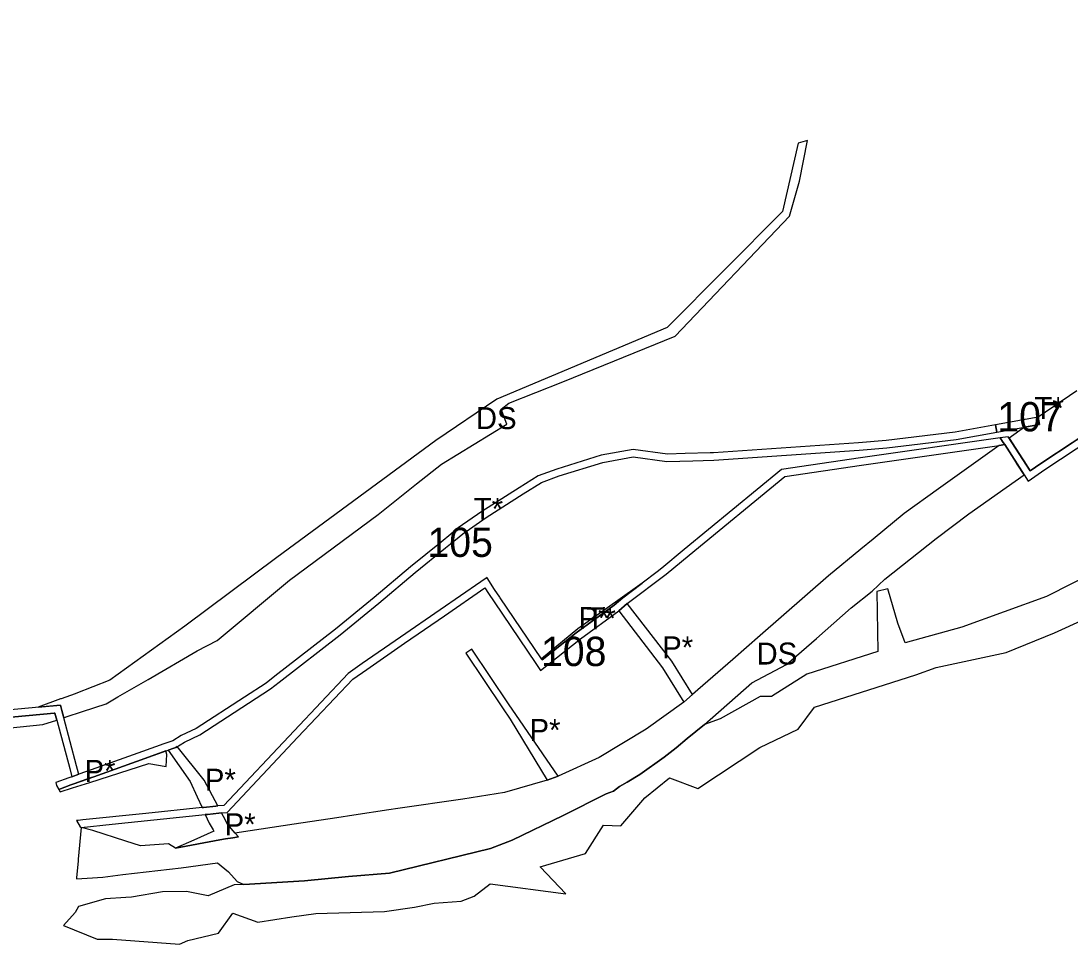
# Model space of a CAD drawing. Extents: x -477304 to -465641, y -1159113 to -1149285.
# Drawn here: x -476117.4 to -475687.9, y -1154887 to -1154509.2 of the extents above; entities that cross this region are included whole.
import ezdxf

# ---------------------------------------------------------------- set-up
doc = ezdxf.new("R2010")
doc.units = 0
for name, color, linetype in [('22', 7, 'Continuous'), ('34', 7, 'Continuous'), ('35', 7, 'Continuous'), ('4', 7, 'Continuous'), ('60', 7, 'Continuous')]:
    doc.layers.add(name, color=color, linetype=linetype)

msp = doc.modelspace()

# ---------------------------------------------------------------- linework, layer by layer
at = {"layer": '22'}
for p, q in [((-475758.44, -1154755.69), (-475762.53, -1154741.69)), ((-475697.53, -1154744.77), (-475732.26, -1154757.29)), ((-475714.08, -1154767.75), (-475694.3, -1154759.7)), ((-475792.53, -1154790), (-475751.05, -1154776.76)), ((-475799.22, -1154799.01), (-475792.53, -1154790)), ((-475849.2, -1154806.7), (-475854.13, -1154810.46)), ((-475844.63, -1154802.88), (-475849.2, -1154806.7)), ((-475854.13, -1154810.46), (-475864.07, -1154817.55)), ((-475861.99, -1154827.13), (-475851.92, -1154818.99)), ((-475851.92, -1154818.99), (-475840.29, -1154823.32)), ((-475874.75, -1154824.37), (-475877.78, -1154825.48)), ((-475916.35, -1154844.45), (-475925.17, -1154847.88)), ((-475925.17, -1154847.88), (-475966.49, -1154857.95)), ((-475894.38, -1154866.48), (-475904.83, -1154855.44)), ((-476030.13, -1154862.72), (-476040.75, -1154867.29)), ((-475931.84, -1154867.36), (-475925.32, -1154862.34)), ((-475925.32, -1154862.34), (-475894.38, -1154866.48)), ((-476040.75, -1154867.29), (-476049.61, -1154865.49)), ((-476095.23, -1154874.14), (-476099.93, -1154879.38)), ((-476099.93, -1154879.38), (-476086.18, -1154884.99)), ((-476049.12, -1154885.62), (-476036.49, -1154882.49)), ((-476086.18, -1154884.99), (-476079.85, -1154885.05))]:
    msp.add_line(p, q, dxfattribs=at)
for points in [[(-475641.33, -1154712.54), (-475655.75, -1154723.67), (-475697.53, -1154744.77)], [(-475694.3, -1154759.7), (-475671.25, -1154749.19), (-475628.72, -1154721.46), (-475627.32, -1154720.53)], [(-475762.53, -1154741.69), (-475767.02, -1154742.69), (-475766.62, -1154767.26), (-475795.73, -1154776.52), (-475810.07, -1154785.67), (-475814.8, -1154785.73), (-475831.1, -1154794.9), (-475837.59, -1154797.1), (-475844.63, -1154802.88)], [(-475732.26, -1154757.29), (-475755.4, -1154763.75), (-475758.44, -1154755.69)], [(-475751.05, -1154776.76), (-475742.66, -1154773.84), (-475714.08, -1154767.75)], [(-475840.29, -1154823.32), (-475814.86, -1154806.55), (-475799.22, -1154799.01)], [(-475864.07, -1154817.55), (-475869.24, -1154820.78), (-475872.38, -1154822.57), (-475874.75, -1154824.37)], [(-475877.78, -1154825.48), (-475895.41, -1154834.42), (-475916.35, -1154844.45)], [(-475878.85, -1154838.35), (-475871.78, -1154838.63), (-475861.99, -1154827.13)], [(-475904.83, -1154855.44), (-475886.23, -1154849.97), (-475878.85, -1154838.35)], [(-475966.49, -1154857.95), (-475983.34, -1154859.42), (-476001.3, -1154861.14)], [(-476001.3, -1154861.14), (-476026.13, -1154862.63), (-476030.13, -1154862.72)], [(-476049.61, -1154865.49), (-476059.4, -1154865.62), (-476072.2, -1154867.83), (-476074.44, -1154868), (-476082.72, -1154868.56), (-476093.86, -1154871.59), (-476095.23, -1154874.14)], [(-475968.58, -1154873.72), (-475956.34, -1154871.9), (-475948.19, -1154870.34), (-475937.16, -1154869.49), (-475931.84, -1154867.36)], [(-476036.49, -1154882.49), (-476030.59, -1154874.38), (-476020.4, -1154878.03), (-476006.43, -1154875.93)], [(-476006.43, -1154875.93), (-475996.67, -1154874.47), (-475968.58, -1154873.72)], [(-476079.85, -1154885.05), (-476052.52, -1154886.99), (-476049.12, -1154885.62)]]:
    msp.add_lwpolyline(points, dxfattribs=at)
at = {"layer": '34'}
for p, q in [((-475863.11, -1154739.28), (-475873.1, -1154746.39)), ((-475871.05, -1154745.28), (-475863.11, -1154739.28)), ((-475873.1, -1154746.39), (-475889.39, -1154757.98)), ((-475869.17, -1154747.62), (-475872.68, -1154750.6)), ((-475872.68, -1154750.6), (-475854.76, -1154773.95)), ((-475850.93, -1154771.26), (-475869.17, -1154747.62)), ((-475889.39, -1154757.98), (-475904.3, -1154770.25)), ((-475842.46, -1154784.88), (-475850.93, -1154771.26)), ((-475854.76, -1154773.95), (-475846.08, -1154788.04)), ((-475846.08, -1154788.04), (-475842.46, -1154784.88)), ((-475920.24, -1154790.36), (-475917.13, -1154794.99)), ((-475917.13, -1154794.99), (-475901.97, -1154819.95)), ((-476054.43, -1154806.66), (-476057.17, -1154807.64)), ((-476042.39, -1154819.88), (-476053.38, -1154806.14)), ((-476057.66, -1154809.45), (-476058.1, -1154807.98)), ((-476057.88, -1154814.34), (-476057.66, -1154809.45)), ((-476057.17, -1154807.64), (-476048.12, -1154820.49)), ((-476088.97, -1154819.02), (-476095.75, -1154821.47)), ((-476087.62, -1154818.53), (-476088.97, -1154819.02)), ((-476036.75, -1154830.49), (-476042.39, -1154819.88)), ((-475901.97, -1154819.95), (-475897.47, -1154818.33)), ((-476101.91, -1154823.69), (-476101.3, -1154824.75)), ((-476048.12, -1154820.49), (-476045.25, -1154826.76)), ((-476045.25, -1154826.76), (-476043.25, -1154831.16)), ((-476043.25, -1154831.16), (-476042.67, -1154831.1)), ((-476042.67, -1154831.1), (-476037.62, -1154830.58)), ((-476037.62, -1154830.58), (-476036.75, -1154830.49)), ((-476040.98, -1154833.94), (-476041.95, -1154834.04)), ((-476041.95, -1154834.04), (-476040.36, -1154837.54)), ((-476036.33, -1154833.46), (-476040.98, -1154833.94)), ((-476035.24, -1154833.35), (-476036.33, -1154833.46)), ((-476034.43, -1154834.87), (-476035.24, -1154833.35)), ((-476032.81, -1154837.91), (-476034.43, -1154834.87)), ((-476038.46, -1154840.8), (-476046.61, -1154844.46)), ((-476040.36, -1154837.54), (-476038.76, -1154840.3)), ((-476038.76, -1154840.3), (-476038.46, -1154840.8)), ((-476029.68, -1154841.62), (-476032.81, -1154837.91)), ((-476054.11, -1154847.83), (-476035.96, -1154844.3)), ((-476046.61, -1154844.46), (-476054.11, -1154847.83)), ((-476035.96, -1154844.3), (-476033.65, -1154843.9)), ((-476033.65, -1154843.9), (-476030.7, -1154843.48)), ((-476030.7, -1154843.48), (-476028.39, -1154843.15)), ((-476028.39, -1154843.15), (-476029.68, -1154841.62))]:
    msp.add_line(p, q, dxfattribs=at)
for points in [[(-475904.3, -1154770.25), (-475904.15, -1154770.49), (-475904, -1154770.7), (-475890.09, -1154759.68), (-475874.54, -1154748.25), (-475871.05, -1154745.28)], [(-475934, -1154767.16), (-475935.24, -1154767.99), (-475920.24, -1154790.36)], [(-475897.47, -1154818.33), (-475917.76, -1154788.68), (-475932.75, -1154766.33), (-475934, -1154767.16)], [(-476053.38, -1154806.14), (-476053.98, -1154806.5), (-476054.43, -1154806.66)], [(-476058.1, -1154807.98), (-476066.67, -1154811.07), (-476087.62, -1154818.53)], [(-476089.16, -1154820.83), (-476065.05, -1154813.06), (-476057.88, -1154814.34)], [(-476095.75, -1154821.47), (-476096.97, -1154821.91), (-476101.91, -1154823.69)], [(-476101.3, -1154824.75), (-476096.32, -1154823.14), (-476089.16, -1154820.83)]]:
    msp.add_lwpolyline(points, dxfattribs=at)
at = {"layer": '35'}
for p, q in [((-475685.2, -1154660.63), (-475700.93, -1154671.42)), ((-475922.61, -1154664.03), (-475947.5, -1154680.92)), ((-475918.51, -1154674.28), (-475920.8, -1154668.13)), ((-475699.88, -1154690.36), (-475667.77, -1154669.13)), ((-475700.93, -1154671.42), (-475700.4, -1154674.37)), ((-475945.25, -1154690.59), (-475918.51, -1154674.28)), ((-475706.58, -1154675.47), (-475712.81, -1154679.95)), ((-475700.4, -1154674.37), (-475706.58, -1154675.47)), ((-475947.5, -1154680.92), (-476012.67, -1154728.85)), ((-475712.81, -1154679.95), (-475707.37, -1154688.4)), ((-475716.95, -1154682.93), (-475741.77, -1154700.75)), ((-475714.68, -1154682.6), (-475716.95, -1154682.93)), ((-475709.85, -1154690.08), (-475714.68, -1154682.6)), ((-475955.49, -1154698.67), (-475945.25, -1154690.59)), ((-475709.83, -1154690.12), (-475709.85, -1154690.08)), ((-475709.81, -1154690.15), (-475709.83, -1154690.12)), ((-475709.26, -1154690.99), (-475709.81, -1154690.15)), ((-475706.66, -1154695.02), (-475709.26, -1154690.99)), ((-475707.37, -1154688.4), (-475707.35, -1154688.42)), ((-475707.35, -1154688.42), (-475706.8, -1154689.27)), ((-475706.8, -1154689.27), (-475704.19, -1154693.32)), ((-475704.19, -1154693.32), (-475699.88, -1154690.36)), ((-475714.09, -1154700.11), (-475706.66, -1154695.02)), ((-475971.18, -1154711.25), (-475955.49, -1154698.67)), ((-475741.77, -1154700.75), (-475755.82, -1154710.84)), ((-476007.43, -1154738.07), (-475971.18, -1154711.25)), ((-475755.82, -1154710.84), (-475768.54, -1154721.28)), ((-475773.59, -1154725.43), (-475786.81, -1154736.27)), ((-475768.54, -1154721.28), (-475773.59, -1154725.43)), ((-476012.67, -1154728.85), (-476050.28, -1154756.97)), ((-476037, -1154762.78), (-476007.43, -1154738.07)), ((-475786.81, -1154736.27), (-475814.84, -1154760.76)), ((-475768.86, -1154742.57), (-475763.79, -1154737.64)), ((-476050.28, -1154756.97), (-476081.05, -1154779.07)), ((-476045.28, -1154767.03), (-476037, -1154762.78)), ((-475814.84, -1154760.76), (-475825.98, -1154770.49)), ((-475804.04, -1154772.54), (-475791.68, -1154761.94)), ((-475825.98, -1154770.49), (-475840.27, -1154782.97)), ((-476095.21, -1154784.55), (-476100.9, -1154786.6)), ((-475842.46, -1154784.88), (-475846.08, -1154788.04)), ((-475840.27, -1154782.97), (-475842.46, -1154784.88)), ((-476101.2, -1154786.71), (-476110.36, -1154790.12)), ((-476100.9, -1154786.6), (-476101.2, -1154786.71)), ((-475846.08, -1154788.04), (-475861.5, -1154799)), ((-476100.64, -1154791.48), (-476099.87, -1154794.38)), ((-476099.87, -1154794.38), (-476098.93, -1154794.07)), ((-476098.93, -1154794.07), (-476092.16, -1154791.84)), ((-476133.97, -1154799.67), (-476108.48, -1154797.21)), ((-476108.48, -1154797.21), (-476102.72, -1154795.32)), ((-475861.5, -1154799), (-475880.64, -1154810.64)), ((-475880.64, -1154810.64), (-475897.47, -1154818.33)), ((-475897.47, -1154818.33), (-475901.97, -1154819.95)), ((-475869.24, -1154820.78), (-475864.07, -1154817.55)), ((-475901.97, -1154819.95), (-475919.37, -1154824.97)), ((-475872.38, -1154822.57), (-475869.24, -1154820.78)), ((-475936.55, -1154827.75), (-475963.04, -1154831.53)), ((-475919.37, -1154824.97), (-475936.55, -1154827.75)), ((-475963.04, -1154831.53), (-475966.77, -1154832.06)), ((-475988.12, -1154835.3), (-476005.51, -1154837.95)), ((-476074.46, -1154844.88), (-476087.95, -1154840.53)), ((-476068.39, -1154846.84), (-476074.46, -1154844.88)), ((-476035.96, -1154844.3), (-476054.11, -1154847.83)), ((-476033.65, -1154843.9), (-476035.96, -1154844.3)), ((-476030.7, -1154843.48), (-476033.65, -1154843.9)), ((-476028.39, -1154843.15), (-476030.7, -1154843.48)), ((-476029.68, -1154841.62), (-476028.39, -1154843.15)), ((-475925.17, -1154847.88), (-475916.35, -1154844.45)), ((-476057.03, -1154845.94), (-476068.39, -1154846.84)), ((-476054.11, -1154847.83), (-476057.03, -1154845.94)), ((-475966.49, -1154857.95), (-475925.17, -1154847.88)), ((-476051.82, -1154855.83), (-476036.88, -1154853.74)), ((-476036.88, -1154853.74), (-476032.42, -1154857.45)), ((-476083.9, -1154859.63), (-476075.68, -1154858.55)), ((-476075.68, -1154858.55), (-476051.82, -1154855.83)), ((-476032.42, -1154857.45), (-476028.91, -1154861.43)), ((-475983.34, -1154859.42), (-475966.49, -1154857.95)), ((-476094.7, -1154860.3), (-476090.22, -1154860.02)), ((-476090.22, -1154860.02), (-476083.9, -1154859.63)), ((-476028.91, -1154861.43), (-476026.13, -1154862.63))]:
    msp.add_line(p, q, dxfattribs=at)
for points in [[(-475799.19, -1154559.23), (-475805.67, -1154587.21), (-475852.85, -1154634.72), (-475922.61, -1154664.03)], [(-475798.7, -1154574.83), (-475795.44, -1154558.14), (-475799.19, -1154559.23)], [(-475920.8, -1154668.13), (-475917.69, -1154665.67), (-475895.52, -1154656.98), (-475849.57, -1154638.2), (-475802.7, -1154589.18), (-475798.7, -1154574.83)], [(-475763.79, -1154737.64), (-475742.69, -1154721.08), (-475729.35, -1154710.9), (-475714.09, -1154700.11)], [(-475791.68, -1154761.94), (-475777.51, -1154749.36), (-475768.86, -1154742.57)], [(-476077.71, -1154785.89), (-476065.3, -1154778.67), (-476045.28, -1154767.03)], [(-475837.59, -1154797.1), (-475818.14, -1154780.14), (-475804.04, -1154772.54)], [(-476081.05, -1154779.07), (-476094.92, -1154784.44), (-476095.21, -1154784.55)], [(-476110.36, -1154790.12), (-476101.23, -1154789.27), (-476101.1, -1154789.74), (-476100.64, -1154791.48)], [(-476092.16, -1154791.84), (-476082.55, -1154788.68), (-476077.71, -1154785.89)], [(-476103.83, -1154792.52), (-476103.86, -1154792.53), (-476131.8, -1154795.14), (-476148.76, -1154794.9)], [(-476102.72, -1154795.32), (-476103.48, -1154792.49), (-476103.83, -1154792.52)], [(-475864.07, -1154817.55), (-475854.13, -1154810.46), (-475849.2, -1154806.7), (-475844.63, -1154802.88), (-475837.59, -1154797.1)], [(-475877.78, -1154825.48), (-475874.75, -1154824.37), (-475872.38, -1154822.57)], [(-475916.35, -1154844.45), (-475895.41, -1154834.42), (-475877.78, -1154825.48)], [(-475966.77, -1154832.06), (-475981.14, -1154834.24), (-475988.12, -1154835.3)], [(-476087.95, -1154840.53), (-476092.69, -1154839.28), (-476093.92, -1154852.23), (-476094, -1154853.04), (-476094.65, -1154859.83), (-476094.7, -1154860.3)], [(-476005.51, -1154837.95), (-476028.03, -1154841.35), (-476029.68, -1154841.62)], [(-476026.13, -1154862.63), (-476001.3, -1154861.14), (-475983.34, -1154859.42)]]:
    msp.add_lwpolyline(points, dxfattribs=at)
at = {"layer": '4'}
for p, q in [((-475700.93, -1154671.42), (-475718.46, -1154674.55)), ((-475700.4, -1154674.37), (-475700.93, -1154671.42)), ((-475718.46, -1154674.55), (-475735.01, -1154677.5)), ((-475718.46, -1154674.55), (-475717.93, -1154677.5)), ((-475717.93, -1154677.5), (-475718.46, -1154674.55)), ((-475717.93, -1154677.5), (-475700.4, -1154674.37)), ((-475716.47, -1154679.83), (-475773.69, -1154688.08)), ((-475713.2, -1154679.36), (-475716.47, -1154679.83)), ((-475715.25, -1154681.71), (-475716.47, -1154679.83)), ((-475716.47, -1154679.83), (-475715.25, -1154681.71)), ((-475714.68, -1154682.6), (-475715.25, -1154681.71)), ((-475715.25, -1154681.71), (-475714.68, -1154682.6)), ((-475704.19, -1154693.32), (-475713.2, -1154679.36)), ((-475866.8, -1154684.59), (-475879.92, -1154686.96)), ((-475835.29, -1154686.01), (-475845.49, -1154686.3)), ((-475773.32, -1154691.06), (-475716.95, -1154682.93)), ((-475716.95, -1154682.93), (-475714.68, -1154682.6)), ((-475714.68, -1154682.6), (-475706.66, -1154695.02)), ((-475842.37, -1154689.21), (-475838.16, -1154689.09)), ((-475706.66, -1154695.02), (-475705.04, -1154697.54)), ((-475945.43, -1154722.52), (-475957.89, -1154732.59)), ((-475853.21, -1154735.56), (-475843.86, -1154727.85)), ((-475957.89, -1154732.59), (-475972.86, -1154745.18)), ((-475926.6, -1154737.01), (-475929.08, -1154738.71)), ((-475926.55, -1154737.1), (-475926.6, -1154737.01)), ((-475856.93, -1154734.61), (-475863.11, -1154739.28)), ((-475929.08, -1154738.71), (-475945.71, -1154750.2)), ((-475944.01, -1154752.67), (-475927.46, -1154741.24)), ((-475927.46, -1154741.24), (-475925.99, -1154743.55)), ((-475863.11, -1154739.28), (-475871.05, -1154745.28)), ((-475972.86, -1154745.18), (-475988.63, -1154758.17)), ((-475925.99, -1154743.55), (-475923.68, -1154746.96)), ((-475945.71, -1154750.2), (-475961.98, -1154761.43)), ((-475923.68, -1154746.96), (-475906.63, -1154772.17)), ((-475960.31, -1154763.93), (-475944.01, -1154752.67)), ((-475988.63, -1154758.17), (-476013.49, -1154777.42)), ((-475961.98, -1154761.43), (-475977.64, -1154772.24)), ((-475975.79, -1154774.61), (-475960.31, -1154763.93)), ((-475906.63, -1154772.17), (-475904.67, -1154775.06)), ((-476016.97, -1154780.18), (-476025.92, -1154785.97)), ((-476013.49, -1154777.42), (-476016.97, -1154780.18)), ((-476099.87, -1154794.38), (-476100.64, -1154791.48)), ((-476102.72, -1154795.32), (-476097.44, -1154815.14)), ((-476094.61, -1154814.09), (-476099.87, -1154794.38)), ((-476051.8, -1154801.71), (-476055.27, -1154803.77)), ((-476055.27, -1154803.77), (-476058.96, -1154805.1)), ((-476097.44, -1154815.14), (-476096.66, -1154818.07)), ((-476093.83, -1154817.01), (-476094.61, -1154814.09)), ((-476097.75, -1154819), (-476103.13, -1154820.94)), ((-476096.53, -1154818.56), (-476097.75, -1154819)), ((-476096.66, -1154818.07), (-476096.53, -1154818.56)), ((-476096.53, -1154818.56), (-476093.69, -1154817.54)), ((-476093.69, -1154817.54), (-476096.53, -1154818.56)), ((-476095.75, -1154821.47), (-476087.62, -1154818.53)), ((-476093.69, -1154817.54), (-476093.83, -1154817.01)), ((-476088.63, -1154815.71), (-476093.69, -1154817.54)), ((-476043.25, -1154831.16), (-476066.27, -1154833.54)), ((-476042.67, -1154831.1), (-476043.25, -1154831.16)), ((-476037.62, -1154830.58), (-476042.67, -1154831.1)), ((-476036.75, -1154830.49), (-476037.62, -1154830.58)), ((-476093.95, -1154836.39), (-476094.61, -1154836.46)), ((-476094.61, -1154836.46), (-476093.12, -1154839.08)), ((-476092.1, -1154836.2), (-476093.95, -1154836.39)), ((-476066.27, -1154833.54), (-476092.1, -1154836.2)), ((-476080.02, -1154837.97), (-476041.95, -1154834.04)), ((-476041.95, -1154834.04), (-476040.98, -1154833.94)), ((-476040.98, -1154833.94), (-476036.33, -1154833.46)), ((-476036.33, -1154833.46), (-476035.24, -1154833.35)), ((-476093.12, -1154839.08), (-476092.69, -1154839.28)), ((-476092.69, -1154839.28), (-476080.02, -1154837.97))]:
    msp.add_line(p, q, dxfattribs=at)
for points in [[(-475705.04, -1154697.54), (-475698.2, -1154692.85), (-475666.13, -1154671.64), (-475663.42, -1154669.9), (-475654.61, -1154663.76), (-475646.58, -1154657.65), (-475637.95, -1154649.25), (-475632.94, -1154643.52), (-475623.98, -1154633.61), (-475616.1, -1154621.77), (-475611.02, -1154612.76), (-475607.44, -1154605.87), (-475605.11, -1154599.32), (-475602.71, -1154588.87), (-475601.48, -1154583.53), (-475594.97, -1154562.13), (-475593.69, -1154555.61), (-475587.15, -1154525.54), (-475583, -1154510.01)], [(-475585.9, -1154509.24), (-475590.07, -1154524.83), (-475596.63, -1154555), (-475597.88, -1154561.4), (-475604.38, -1154582.76), (-475605.63, -1154588.2), (-475607.99, -1154598.48), (-475610.2, -1154604.67), (-475613.66, -1154611.33), (-475618.66, -1154620.2), (-475626.35, -1154631.76), (-475635.18, -1154641.53), (-475640.13, -1154647.18), (-475648.54, -1154655.37), (-475656.38, -1154661.33), (-475665.09, -1154667.41), (-475667.77, -1154669.13), (-475699.88, -1154690.36), (-475704.19, -1154693.32)], [(-475838.16, -1154689.09), (-475833.71, -1154688.97), (-475774.24, -1154684.86), (-475762.91, -1154683.98), (-475734.56, -1154680.47), (-475717.93, -1154677.5)], [(-475735.01, -1154677.5), (-475763.21, -1154680.99), (-475774.46, -1154681.87), (-475833.86, -1154685.97), (-475835.29, -1154686.01)], [(-475845.49, -1154686.3), (-475852.76, -1154686.51), (-475866.8, -1154684.59)], [(-476087.62, -1154818.53), (-476066.67, -1154811.07), (-476057.94, -1154807.92), (-476053.98, -1154806.5), (-476050.38, -1154804.36), (-476044.15, -1154801.35), (-476024.29, -1154788.49), (-476015.22, -1154782.62), (-476011.64, -1154779.78), (-475986.76, -1154760.51), (-475970.94, -1154747.49), (-475955.98, -1154734.9), (-475943.54, -1154724.85), (-475939.56, -1154721.6), (-475936.53, -1154719.09), (-475927, -1154712.44), (-475911.78, -1154702.79), (-475904.29, -1154698.12), (-475897.03, -1154695.44), (-475879.2, -1154689.88), (-475866.73, -1154687.63), (-475852.92, -1154689.52), (-475842.37, -1154689.21)], [(-475879.92, -1154686.96), (-475898, -1154692.6), (-475905.62, -1154695.41)], [(-475773.69, -1154688.08), (-475806, -1154692.74), (-475845.85, -1154725.6)], [(-475843.86, -1154727.85), (-475804.74, -1154695.59), (-475773.32, -1154691.06)], [(-475905.62, -1154695.41), (-475913.38, -1154700.25), (-475928.66, -1154709.94), (-475938.35, -1154716.7)], [(-475938.35, -1154716.7), (-475941.47, -1154719.28), (-475945.43, -1154722.52)], [(-475845.85, -1154725.6), (-475855.07, -1154733.2), (-475856.93, -1154734.61)], [(-475921.32, -1154745.1), (-475923.48, -1154741.9), (-475926.55, -1154737.1)], [(-475872.68, -1154750.6), (-475869.17, -1154747.62), (-475853.21, -1154735.56)], [(-475904.3, -1154770.25), (-475921.2, -1154745.28), (-475921.32, -1154745.1)], [(-475871.05, -1154745.28), (-475874.54, -1154748.25), (-475890.09, -1154759.68), (-475904, -1154770.7), (-475904.15, -1154770.49), (-475904.3, -1154770.25)], [(-475904.67, -1154775.06), (-475888.27, -1154762.06), (-475872.68, -1154750.6)], [(-475977.64, -1154772.24), (-475983.48, -1154776.27), (-476005.56, -1154799.69)], [(-476003.98, -1154802.39), (-475981.51, -1154778.56), (-475975.79, -1154774.61)], [(-476100.64, -1154791.48), (-476101.1, -1154789.74), (-476101.23, -1154789.27), (-476131.92, -1154792.14), (-476138.63, -1154792.04), (-476146.9, -1154791.93), (-476148.19, -1154791.91), (-476149.14, -1154791.9)], [(-476025.92, -1154785.97), (-476045.62, -1154798.73), (-476051.8, -1154801.71)], [(-476148.76, -1154794.9), (-476131.8, -1154795.14), (-476103.86, -1154792.53), (-476103.83, -1154792.52)], [(-476103.83, -1154792.52), (-476103.48, -1154792.49), (-476102.72, -1154795.32)], [(-476005.56, -1154799.69), (-476034.37, -1154830.25), (-476036.75, -1154830.49)], [(-476035.24, -1154833.35), (-476032.95, -1154833.12), (-476003.98, -1154802.39)], [(-476058.96, -1154805.1), (-476067.68, -1154808.25), (-476088.63, -1154815.71)], [(-476103.13, -1154820.94), (-476102.8, -1154822.12), (-476101.91, -1154823.69)], [(-476101.91, -1154823.69), (-476096.97, -1154821.91), (-476095.75, -1154821.47)]]:
    msp.add_lwpolyline(points, dxfattribs=at)

# ---------------------------------------------------------------- texts
at = {"layer": '34'}
for p in [(-475889.13, -1154758.09), (-475854.91, -1154770.09), (-475909.22, -1154803.9), (-476091.4, -1154820.64), (-476042.12, -1154824.26), (-476034.03, -1154842.49)]:
    msp.add_text('P*', height=9, dxfattribs=at).set_placement(p)
at = {"layer": '35'}
for p in [(-475931.19, -1154676.26), (-475816.3, -1154772.61)]:
    msp.add_text('DS', height=9, dxfattribs=at).set_placement(p)
at = {"layer": '4'}
for p in [(-475702.5, -1154672.11), (-475932.02, -1154713.39), (-475885.89, -1154758.15)]:
    msp.add_text('T*', height=9, dxfattribs=at).set_placement(p)
at = {"layer": '60'}
for s, p in [('107', (-475717.69, -1154677.19)), ('105', (-475950.97, -1154728.57)), ('108', (-475904.48, -1154773.24))]:
    msp.add_text(s, height=12, dxfattribs=at).set_placement(p)

doc.saveas('drawing.dxf')
